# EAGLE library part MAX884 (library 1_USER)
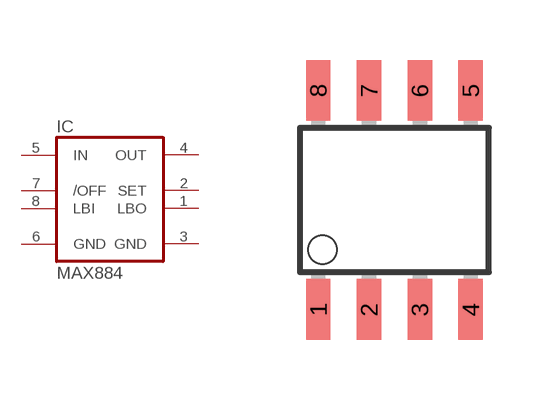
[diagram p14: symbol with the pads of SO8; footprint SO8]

Designator prefix IC

## MAX884  [SO8]
1  LBO  out
2  SET  in
3  GND  pwr
4  OUT  out
5  IN  in
6  GND  pwr
7  /OFF  in
8  LBI  in

## Footprint SO8 (pad centres in mm)
smd 0.61 x 1.524: 1 -1.27,-2.743; 2 0,-2.743; 3 1.27,-2.743; 4 2.54,-2.743; 5 2.54,2.743; 6 1.27,2.743; 7 0,2.743; 8 -1.27,2.743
